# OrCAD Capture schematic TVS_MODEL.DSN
size A
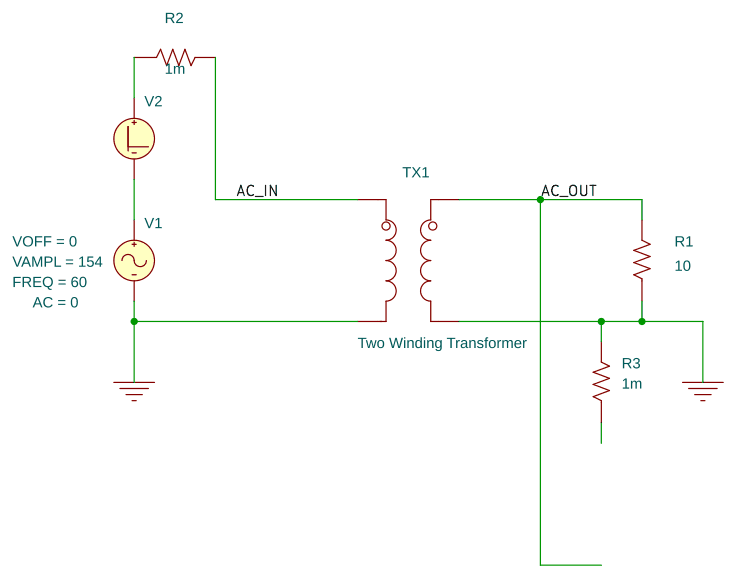
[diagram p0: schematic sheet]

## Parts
R1  10  [AXRC05]
R2  1m  [AXRC05]
R3  1m  [AXRC05]
TX1  Two Winding Transformer
V1  VSIN
V2  VImpulse

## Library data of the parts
R1-R3 = R
TX1 = ST: AppProp: modelname=ST_Model,LP1=5,RP1=10m,Rs1=10m,N=0.1,LI=100n
V1 = VSIN: AC: 0; AppProp: Sine$Voltage$0$-1; DC: 0; FREQ: 60; VAMPL: 154; VOFF: 0
V2 = VImpulse: AppProp: Impulse$Voltage$0$-1; D: 40m

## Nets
0: R1.1 R3.2 TX1.2 TX1.4 V1.2(-)
AC_IN: R2.2 TX1.1
AC_OUT: R1.2 TX1.3
N00459: V1.1(+) V2.2(-)
N00477: R2.1 V2.1(+)

Not connected (* = marked no-connect by the designer): R3 1
